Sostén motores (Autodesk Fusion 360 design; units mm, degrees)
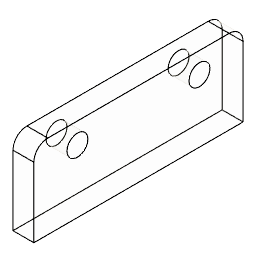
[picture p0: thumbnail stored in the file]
part number: 2026-07-18-00-36-02-678
sketch "Boceto1" plane through (0, 0, 0) normal (0, 0, 1) x axis (1, 0, 0)
  line L1 (3, 0) -> (0, 0)
  line L2 (3, 30) -> (3, 0)
  line L3 (0, 30) -> (3, 30)
  line L4 (0, 0) -> (0, 30)
  point P1 (0, 0)
  point P2 (0, 0)
  point P3 (3, 0)
  point P4 (3, 30)
  coincident P1 P2
  horizontal L1
  perpendicular L1 L2
  perpendicular L2 L3
  perpendicular L1 L4
  dimension "d1" distance P3 P4 = 30
extrude "Extruir1" new body sketch "Boceto1" along normal blind 6
sketch "Boceto2" plane through (3, 0, 0) normal (1, 0, 0) x axis (0, 1, 0)
  line L1 (30, 0) -> (0, 0)
  line L2 (30, 6) -> (30, 0)
  line L3 (0, 6) -> (30, 6)
  line L4 (0, 0) -> (0, 6)
  line L5 (4.75, 6) -> (0, 6)
  line L6 (4.75, 4.5) -> (4.75, 6)
  line L7 (4.75, 3) -> (4.75, 4.5)
  line L8 (25.25, 6) -> (30, 6)
  line L9 (25.25, 3) -> (25.25, 6)
  circle C1 centre (4.75, 3) radius 1.5
  circle C2 centre (25.25, 3) radius 1.5
  point P5 (0, 6)
  point P6 (0, 6)
  point P9 (4.75, 3)
  point P10 (4.75, 3)
  point P8 (4.75, 4.5)
  point P4 (30, 6)
  point P11 (30, 6)
  point P13 (25.25, 3)
  point P14 (25.25, 3)
  point P7 (4.75, 6)
  point P12 (25.25, 6)
  coincident P5 P6
  perpendicular L4 L5
  perpendicular L3 L6
  perpendicular L3 L7
  coincident P9 P10
  coincident P8 C1
  coincident P4 P11
  perpendicular L2 L8
  perpendicular L3 L9
  coincident P13 P14
  dimension "d4" distance P6 P7 = 4.75
  dimension "d5" distance P7 P8 = 1.5
  dimension "d6" distance P11 P12 = 4.75
extrude "Extruir2" cut sketch "Boceto2" profile of C1 C2 against normal blind 6
extrude "Extruir3" add of existing geometry blind 3
fillet "Empalme" radius 2
sketch "Boceto3" plane through (3, 0, 0) normal (1, 0, 0) x axis (0, 1, 0)
  line L1 (2, 6) -> (28, 6)
  line L2 (0, -3) -> (0, 4)
  line L3 (30, -3) -> (0, -3)
  line L4 (30, 4) -> (30, -3)
  line L5 (15, -3) -> (0, -3)
  arc A1 centre (28, 4) radius 2 clockwise from (28, 6) to (30, 4)
  arc A2 centre (2, 4) radius 2 clockwise from (0, 4) to (2, 6)
  circle C1 centre (6.25, 3) radius 1.5
  circle C2 centre (23.75, 3) radius 1.5
  point P8 (0, -3)
  point P10 (0, -3)
  point P11 (15, -3)
  coincident P8 P10
  midpoint L3 P11
extrude "Extruir4" add sketch "Boceto3" profile of C1 C2 against normal blind 3
extrude "Extruir5" cut sketch "Boceto3" profile of C1 C2 against normal blind 3
extrude "Extruir6" add sketch "Boceto3" profile of C1 against normal blind 3
extrude "Extruir7" cut sketch "Boceto2" profile of C1 against normal blind 3
extrude "Extruir8" add sketch "Boceto2" profile of C1 against normal blind 3
extrude "Extruir9" cut sketch "Boceto3" profile of C1 against normal blind 3
extrude "Extruir10" add of existing geometry blind 3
